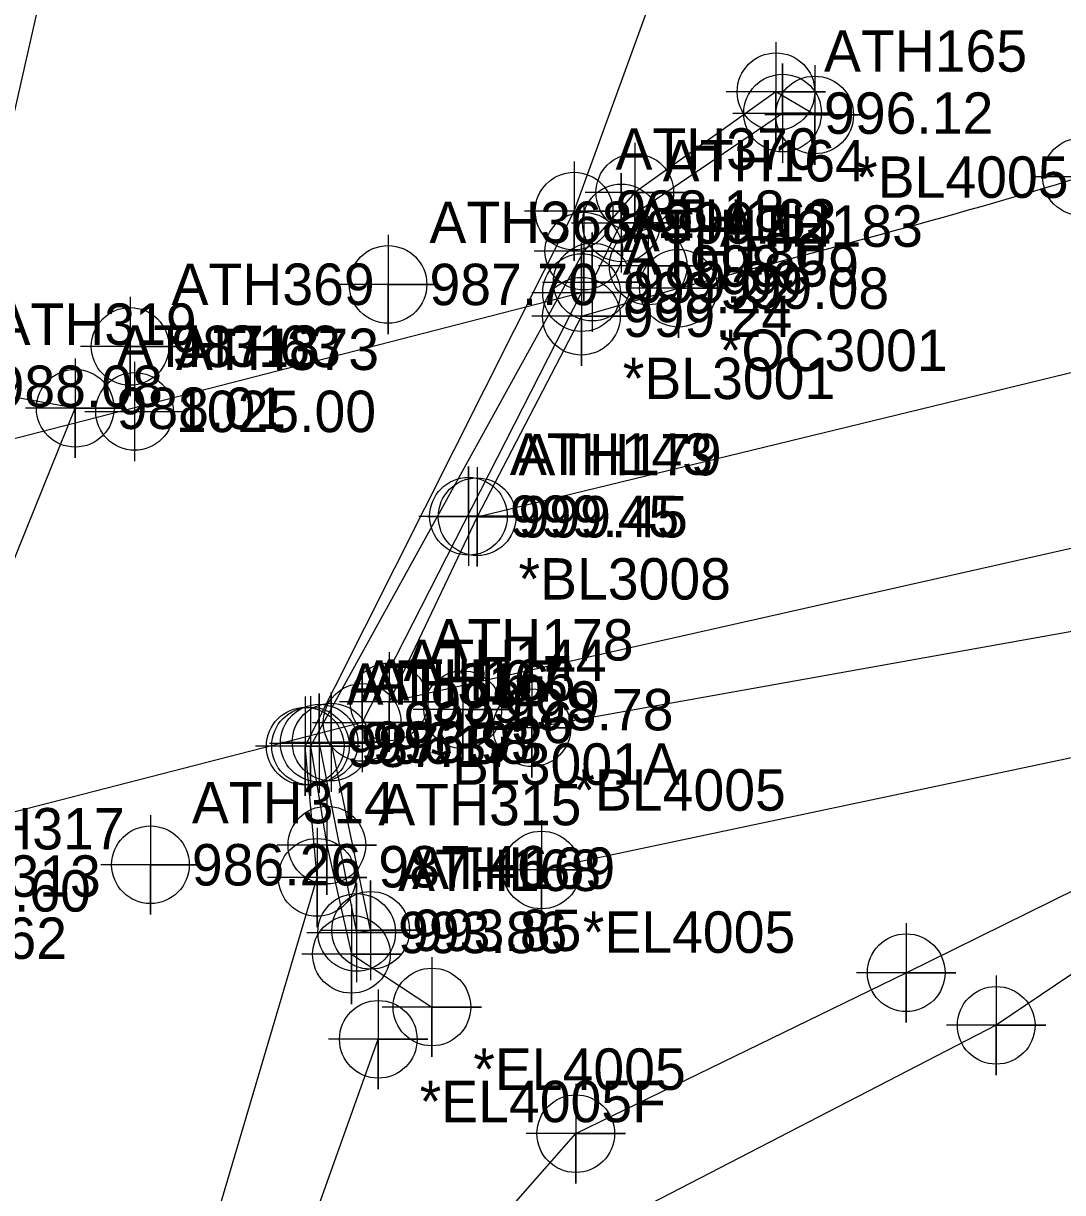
# Model space of a CAD drawing. Extents: x 1116680 to 1117499, y 661040 to 661703.
# Drawn here: x 1117062.7 to 1117125.5, y 661332.7 to 661403.3 of the extents above; entities that cross this region are included whole.
import ezdxf

# ---------------------------------------------------------------- set-up
doc = ezdxf.new("R2010")
doc.units = 0
for name, color, linetype in [('Cogo Default Point CELL', 7, 'Continuous'), ('COGO Default Point Elevation', 7, 'Continuous'), ('COGO Default Point Number', 7, 'Continuous'), ('Exist DTM Breakline', 7, 'Continuous'), ('Exist DTM Breakline Cogo Comment', 7, 'Continuous'), ('Exist DTM Breakline Cogo Point CELL', 7, 'Continuous'), ('Exist DTM Crownline', 7, 'Continuous'), ('Exist DTM Crownline Cogo Comment', 7, 'Continuous'), ('Exist DTM Crownline Cogo Elevation', 7, 'Continuous'), ('Exist DTM Crownline Cogo Number', 7, 'Continuous'), ('Exist DTM Crownline Cogo Point CELL', 7, 'Continuous'), ('Exist DTM Drainline Cogo Elevation', 7, 'Continuous'), ('Exist DTM Drainline Cogo Number', 7, 'Continuous'), ('Exist DTM Drainline Cogo Point CELL', 7, 'Continuous'), ('Exist DTM Regular Point Underwater CELL', 7, 'Continuous'), ('Exist DTM Regular Point Underwater Cogo Elevation', 7, 'Continuous'), ('Exist DTM Regular Point Underwater Cogo Number', 7, 'Continuous'), ('Exist Guardrail Cogo Elevation', 7, 'Continuous'), ('Exist Guardrail Cogo Point CELL', 7, 'Continuous'), ('Exist Hydro Stream or Body of Water', 7, 'Continuous'), ('Exist Roads EOP', 7, 'Continuous'), ('Exist Roads EOP Cogo Comment', 7, 'Continuous'), ('Exist Roads EOP Cogo Elevation', 7, 'Continuous'), ('Exist Roads EOP Cogo Number', 7, 'Continuous'), ('Exist Roads EOP Cogo Point CELL', 7, 'Continuous'), ('Exist Structure Major Bridge Seam Cogo Elevation', 7, 'Continuous'), ('Exist Structure Major Bridge Seam Cogo Number', 7, 'Continuous'), ('Exist Structure Major Bridge Seam Cogo Point CELL', 7, 'Continuous'), ('Exist Structure Major Bridge WW Cogo Elevation', 7, 'Continuous'), ('Exist Structure Major Bridge WW Cogo Number', 7, 'Continuous'), ('Exist Structure Major Bridge WW Cogo Point CELL', 7, 'Continuous'), ('Exist Structure Major Deck Tunnel Box Culvert', 7, 'Continuous')]:
    doc.layers.add(name, color=color, linetype=linetype)

msp = doc.modelspace()

# ---------------------------------------------------------------- linework, layer by layer
at = {"layer": 'Cogo Default Point CELL'}
for points in [[(1117069.447, 661382.896), (1117069.447, 661379.896)], [(1117066.447, 661379.896), (1117069.447, 661379.896)], [(1117069.447, 661379.896), (1117072.447, 661379.896)], [(1117069.447, 661379.896), (1117069.447, 661376.896)]]:
    msp.add_lwpolyline(points, dxfattribs=at)
msp.add_circle((1117069.447, 661379.896), 2.344, dxfattribs=at)
at = {"layer": 'Exist DTM Breakline'}
msp.add_line((1117136.948, 661361.295), (1117094.014, 661352.219), dxfattribs=at)
for points in [[(1117110.514, 661397.787), (1117108.176, 661399.189), (1117099.651, 661393.108), (1117096.571, 661389.572), (1117080.072, 661359.7), (1117081.059, 661353.723), (1117082.542, 661347.13), (1117087.401, 661343.949)], [(1117097.08, 661387.704), (1117098.837, 661391.274), (1117108.577, 661397.9)], [(1117093.445, 661360.799), (1117137.626, 661368.708), (1117143.021, 661357.384), (1117121.473, 661342.844), (1117095.236, 661329.298), (1117090.897, 661311.231), (1117084.978, 661291.24), (1117074.985, 661245.735)], [(1117081.313, 661359.936), (1117080.595, 661359.877), (1117082.857, 661348.449), (1117083.703, 661348.578), (1117081.313, 661359.936)], [(1117067.72, 661245.781), (1117079.092, 661299.504), (1117088.264, 661327.406), (1117096.09, 661336.305), (1117116.041, 661346.019), (1117139.594, 661357.628)], [(1117040.467, 661266.201), (1117071.81, 661307.445), (1117084.165, 661341.998)]]:
    msp.add_lwpolyline(points, dxfattribs=at)
at = {"layer": 'Exist DTM Breakline Cogo Point CELL'}
for points in [[(1117108.176, 661402.189), (1117108.176, 661396.189), (1117108.176, 661399.189), (1117111.176, 661399.189), (1117105.176, 661399.189)], [(1117110.514, 661400.787), (1117110.514, 661394.787), (1117110.514, 661397.787), (1117113.514, 661397.787), (1117107.514, 661397.787)], [(1117099.651, 661396.108), (1117099.651, 661390.108), (1117099.651, 661393.108), (1117102.651, 661393.108), (1117096.651, 661393.108)], [(1117096.571, 661392.572), (1117096.571, 661386.572), (1117096.571, 661389.572), (1117099.571, 661389.572), (1117093.571, 661389.572)], [(1117093.445, 661363.799), (1117093.445, 661357.799), (1117093.445, 661360.799), (1117096.445, 661360.799), (1117090.445, 661360.799)], [(1117080.072, 661362.7), (1117080.072, 661356.7), (1117080.072, 661359.7), (1117083.072, 661359.7), (1117077.072, 661359.7)], [(1117081.059, 661356.723), (1117081.059, 661350.723), (1117081.059, 661353.723), (1117084.059, 661353.723), (1117078.059, 661353.723)], [(1117094.014, 661355.219), (1117094.014, 661349.219), (1117094.014, 661352.219), (1117097.014, 661352.219), (1117091.014, 661352.219)], [(1117082.542, 661350.13), (1117082.542, 661344.13), (1117082.542, 661347.13), (1117085.542, 661347.13), (1117079.542, 661347.13)], [(1117116.041, 661349.019), (1117116.041, 661343.019), (1117116.041, 661346.019), (1117119.041, 661346.019), (1117113.041, 661346.019)], [(1117087.401, 661346.949), (1117087.401, 661340.949), (1117087.401, 661343.949), (1117090.401, 661343.949), (1117084.401, 661343.949)], [(1117121.473, 661345.844), (1117121.473, 661339.844), (1117121.473, 661342.844), (1117124.473, 661342.844), (1117118.473, 661342.844)], [(1117084.165, 661344.998), (1117084.165, 661338.998), (1117084.165, 661341.998), (1117087.165, 661341.998), (1117081.165, 661341.998)], [(1117096.09, 661339.305), (1117096.09, 661333.305), (1117096.09, 661336.305), (1117099.09, 661336.305), (1117093.09, 661336.305)]]:
    msp.add_lwpolyline(points, dxfattribs=at)
for centre in [(1117108.176, 661399.189), (1117110.514, 661397.787), (1117099.651, 661393.108), (1117096.571, 661389.572), (1117093.445, 661360.799), (1117080.072, 661359.7), (1117081.059, 661353.723), (1117094.014, 661352.219), (1117082.542, 661347.13), (1117116.041, 661346.019), (1117087.401, 661343.949), (1117121.473, 661342.844), (1117084.165, 661341.998), (1117096.09, 661336.305)]:
    msp.add_circle(centre, 2.344, dxfattribs=at)
at = {"layer": 'Exist DTM Crownline'}
msp.add_line((1117090.13, 661373.539), (1117128.608, 661382.881), dxfattribs=at)
at = {"layer": 'Exist DTM Crownline Cogo Point CELL'}
msp.add_lwpolyline([(1117090.13, 661376.539), (1117090.13, 661370.539), (1117090.13, 661373.539), (1117093.13, 661373.539), (1117087.13, 661373.539)], dxfattribs=at)
msp.add_circle((1117090.13, 661373.539), 2.344, dxfattribs=at)
at = {"layer": 'Exist DTM Drainline Cogo Point CELL'}
for points in [[(1117095.986, 661394.983), (1117095.986, 661388.983), (1117095.986, 661391.983), (1117098.986, 661391.983), (1117092.986, 661391.983)], [(1117065.864, 661383.085), (1117065.864, 661377.085), (1117065.864, 661380.085), (1117068.864, 661380.085), (1117062.864, 661380.085)], [(1117079.751, 661362.687), (1117079.751, 661356.687), (1117079.751, 661359.687), (1117082.751, 661359.687), (1117076.751, 661359.687)], [(1117080.473, 661354.773), (1117080.473, 661348.773), (1117080.473, 661351.773), (1117083.473, 661351.773), (1117077.473, 661351.773)]]:
    msp.add_lwpolyline(points, dxfattribs=at)
for centre in [(1117095.986, 661391.983), (1117065.864, 661380.085), (1117079.751, 661359.687), (1117080.473, 661351.773)]:
    msp.add_circle(centre, 2.344, dxfattribs=at)
at = {"layer": 'Exist DTM Regular Point Underwater CELL'}
for points in [[(1117084.753, 661390.559), (1117084.753, 661384.559), (1117084.753, 661387.559), (1117087.753, 661387.559), (1117081.753, 661387.559)], [(1117069.181, 661386.82), (1117069.181, 661380.82), (1117069.181, 661383.82), (1117072.181, 661383.82), (1117066.181, 661383.82)], [(1117070.409, 661355.534), (1117070.409, 661349.534), (1117070.409, 661352.534), (1117073.409, 661352.534), (1117067.409, 661352.534)]]:
    msp.add_lwpolyline(points, dxfattribs=at)
for centre in [(1117084.753, 661387.559), (1117069.181, 661383.82), (1117070.409, 661352.534)]:
    msp.add_circle(centre, 2.344, dxfattribs=at)
at = {"layer": 'Exist Guardrail Cogo Point CELL'}
for points in [[(1117100.46, 661391.675), (1117100.46, 661385.675), (1117100.46, 661388.675), (1117103.46, 661388.675), (1117097.46, 661388.675)], [(1117089.265, 661364.896), (1117089.265, 661358.896), (1117089.265, 661361.896), (1117092.265, 661361.896), (1117086.265, 661361.896)]]:
    msp.add_lwpolyline(points, dxfattribs=at)
for centre in [(1117100.46, 661388.675), (1117089.265, 661361.896)]:
    msp.add_circle(centre, 2.344, dxfattribs=at)
at = {"layer": 'Exist Hydro Stream or Body of Water'}
for points in [[(1116885.259, 661065.084), (1116909.522, 661128.826), (1116941.429, 661187.261), (1116973.299, 661231.015), (1117008.806, 661288.675), (1117028.625, 661329.39), (1117037.259, 661346.044), (1117054.084, 661350.959), (1117065.864, 661380.085), (1117058.435, 661381.413), (1117066.561, 661417.266), (1117077.352, 661449.252), (1117098.924, 661488.98)], [(1116999.252, 661212.663), (1117035.553, 661269.03), (1117067.842, 661309.057), (1117080.473, 661351.773), (1117079.751, 661359.687), (1117095.986, 661391.983), (1117110.725, 661432.453), (1117125.362, 661468.034)]]:
    msp.add_lwpolyline(points, dxfattribs=at)
at = {"layer": 'Exist Roads EOP'}
for p, q in [((1117096.428, 661385.641), (1117102.286, 661387.333)), ((1117084.815, 661362.36), (1117131.334, 661372.856))]:
    msp.add_line(p, q, dxfattribs=at)
msp.add_lwpolyline([(1117096.428, 661385.641), (1117090.13, 661373.539), (1117084.815, 661362.36)], dxfattribs=at)
msp.add_spline([(1117102.286, 661387.333), (1117126.621, 661394.057), (1117156.418, 661404.979), (1117187.204, 661421.689), (1117219.891, 661448.41), (1117247.012, 661480.823), (1117275.546, 661531.18), (1117296.661, 661577.27), (1117320.803, 661635.676)], degree=3, dxfattribs=at)
at = {"layer": 'Exist Roads EOP Cogo Point CELL'}
for points in [[(1117126.621, 661397.057), (1117126.621, 661391.057), (1117126.621, 661394.057), (1117129.621, 661394.057), (1117123.621, 661394.057)], [(1117102.286, 661390.333), (1117102.286, 661384.333), (1117102.286, 661387.333), (1117105.286, 661387.333), (1117099.286, 661387.333)], [(1117096.428, 661388.641), (1117096.428, 661382.641), (1117096.428, 661385.641), (1117099.428, 661385.641), (1117093.428, 661385.641)], [(1117084.815, 661365.36), (1117084.815, 661359.36), (1117084.815, 661362.36), (1117087.815, 661362.36), (1117081.815, 661362.36)]]:
    msp.add_lwpolyline(points, dxfattribs=at)
for centre in [(1117126.621, 661394.057), (1117102.286, 661387.333), (1117096.428, 661385.641), (1117084.815, 661362.36)]:
    msp.add_circle(centre, 2.344, dxfattribs=at)
at = {"layer": 'Exist Structure Major Bridge Seam Cogo Point CELL'}
for points in [[(1117093.438, 661387.065), (1117099.438, 661387.065), (1117096.438, 661387.065), (1117096.438, 661390.065), (1117096.438, 661384.065)], [(1117086.61, 661373.568), (1117092.61, 661373.568), (1117089.61, 661373.568), (1117089.61, 661376.568), (1117089.61, 661370.568)], [(1117080.188, 661361.127), (1117086.188, 661361.127), (1117083.188, 661361.127), (1117083.188, 661364.127), (1117083.188, 661358.127)]]:
    msp.add_lwpolyline(points, dxfattribs=at)
for centre in [(1117096.438, 661387.065), (1117089.61, 661373.568), (1117083.188, 661361.127)]:
    msp.add_circle(centre, 2.344, dxfattribs=at)
at = {"layer": 'Exist Structure Major Bridge WW Cogo Point CELL'}
for points in [[(1117105.577, 661397.9), (1117111.577, 661397.9), (1117108.577, 661397.9), (1117108.577, 661400.9), (1117108.577, 661394.9)], [(1117095.837, 661391.274), (1117101.837, 661391.274), (1117098.837, 661391.274), (1117098.837, 661394.274), (1117098.837, 661388.274)], [(1117094.08, 661387.704), (1117100.08, 661387.704), (1117097.08, 661387.704), (1117097.08, 661390.704), (1117097.08, 661384.704)], [(1117077.595, 661359.877), (1117083.595, 661359.877), (1117080.595, 661359.877), (1117080.595, 661362.877), (1117080.595, 661356.877)], [(1117078.313, 661359.936), (1117084.313, 661359.936), (1117081.313, 661359.936), (1117081.313, 661362.936), (1117081.313, 661356.936)], [(1117079.857, 661348.449), (1117085.857, 661348.449), (1117082.857, 661348.449), (1117082.857, 661351.449), (1117082.857, 661345.449)], [(1117080.703, 661348.578), (1117086.703, 661348.578), (1117083.703, 661348.578), (1117083.703, 661351.578), (1117083.703, 661345.578)]]:
    msp.add_lwpolyline(points, dxfattribs=at)
for centre in [(1117108.577, 661397.9), (1117098.837, 661391.274), (1117097.08, 661387.704), (1117080.595, 661359.877), (1117081.313, 661359.936), (1117082.857, 661348.449), (1117083.703, 661348.578)]:
    msp.add_circle(centre, 2.344, dxfattribs=at)
at = {"layer": 'Exist Structure Major Deck Tunnel Box Culvert'}
msp.add_lwpolyline([(1117031.737, 661370.434), (1117096.438, 661387.065), (1117083.188, 661361.127), (1117020.55, 661345.005), (1117031.737, 661370.434)], dxfattribs=at)

# ---------------------------------------------------------------- texts
at = {"layer": 'COGO Default Point Elevation'}
msp.add_text('1025.00', height=2.5, dxfattribs=at).set_placement((1117071.947, 661378.646))
at = {"layer": 'COGO Default Point Number'}
msp.add_text('ATH373', height=2.5, dxfattribs=at).set_placement((1117071.947, 661382.396))
at = {"layer": 'Exist DTM Breakline Cogo Comment'}
for s, p in [('*BL4005', (1117113.014, 661392.787)), ('*BL4005', (1117095.945, 661355.799)), ('*EL4005', (1117096.514, 661347.219)), ('*EL4005', (1117089.901, 661338.949)), ('*EL4005F', (1117086.665, 661336.998))]:
    msp.add_text(s, height=2.5, dxfattribs=at).set_placement(p)
at = {"layer": 'Exist DTM Crownline Cogo Comment'}
msp.add_text('*BL3008', height=2.5, dxfattribs=at).set_placement((1117092.63, 661368.539))
at = {"layer": 'Exist DTM Crownline Cogo Elevation'}
msp.add_text('999.45', height=2.5, dxfattribs=at).set_placement((1117092.63, 661372.289))
at = {"layer": 'Exist DTM Crownline Cogo Number'}
msp.add_text('ATH179', height=2.5, dxfattribs=at).set_placement((1117092.63, 661376.039))
at = {"layer": 'Exist DTM Drainline Cogo Elevation'}
for s, p in [('988.18', (1117098.486, 661390.733)), ('988.08', (1117060.935, 661380.163)), ('988.01', (1117068.364, 661378.835)), ('987.17', (1117082.251, 661358.437)), ('987.46', (1117084.166, 661351.166)), ('987.60', (1117056.584, 661349.709))]:
    msp.add_text(s, height=2.5, dxfattribs=at).set_placement(p)
at = {"layer": 'Exist DTM Drainline Cogo Number'}
for s, p in [('ATH370', (1117098.486, 661394.483)), ('ATH319', (1117060.935, 661383.913)), ('ATH318', (1117068.364, 661382.585)), ('ATH316', (1117082.251, 661362.187)), ('ATH315', (1117084.166, 661354.916)), ('ATH317', (1117056.584, 661353.459))]:
    msp.add_text(s, height=2.5, dxfattribs=at).set_placement(p)
at = {"layer": 'Exist DTM Regular Point Underwater Cogo Elevation'}
for s, p in [('987.70', (1117087.253, 661386.309)), ('987.63', (1117071.681, 661382.57)), ('986.26', (1117072.909, 661351.284)), ('987.62', (1117055.144, 661346.854))]:
    msp.add_text(s, height=2.5, dxfattribs=at).set_placement(p)
at = {"layer": 'Exist DTM Regular Point Underwater Cogo Number'}
for s, p in [('ATH368', (1117087.253, 661390.059)), ('ATH369', (1117071.681, 661386.32)), ('ATH314', (1117072.909, 661355.034)), ('ATH313', (1117055.144, 661350.604))]:
    msp.add_text(s, height=2.5, dxfattribs=at).set_placement(p)
at = {"layer": 'Exist Guardrail Cogo Elevation'}
for s, p in [('998.59', (1117102.96, 661387.425)), ('998.78', (1117091.765, 661360.646))]:
    msp.add_text(s, height=2.5, dxfattribs=at).set_placement(p)
at = {"layer": 'Exist Roads EOP Cogo Comment'}
for s, p in [('*OC3001', (1117104.786, 661382.333)), ('*BL3001', (1117098.928, 661380.641)), ('*BL3001A', (1117087.315, 661357.36))]:
    msp.add_text(s, height=2.5, dxfattribs=at).set_placement(p)
at = {"layer": 'Exist Roads EOP Cogo Elevation'}
for s, p in [('999.08', (1117104.786, 661386.083)), ('999.24', (1117098.928, 661384.391)), ('999.29', (1117087.315, 661361.11))]:
    msp.add_text(s, height=2.5, dxfattribs=at).set_placement(p)
at = {"layer": 'Exist Roads EOP Cogo Number'}
for s, p in [('ATH183', (1117104.786, 661389.833)), ('ATH180', (1117098.928, 661388.141)), ('ATH178', (1117087.315, 661364.86))]:
    msp.add_text(s, height=2.5, dxfattribs=at).set_placement(p)
at = {"layer": 'Exist Structure Major Bridge Seam Cogo Elevation'}
for s, p in [('999.22', (1117098.938, 661385.815)), ('999.45', (1117092.11, 661372.318)), ('999.56', (1117085.688, 661359.877))]:
    msp.add_text(s, height=2.5, dxfattribs=at).set_placement(p)
at = {"layer": 'Exist Structure Major Bridge Seam Cogo Number'}
for s, p in [('ATH142', (1117098.938, 661389.565)), ('ATH143', (1117092.11, 661376.068)), ('ATH144', (1117085.688, 661363.627))]:
    msp.add_text(s, height=2.5, dxfattribs=at).set_placement(p)
at = {"layer": 'Exist Structure Major Bridge WW Cogo Elevation'}
for s, p in [('996.12', (1117111.077, 661396.65)), ('999.12', (1117101.337, 661390.024)), ('999.09', (1117099.58, 661386.454)), ('996.93', (1117083.813, 661358.686)), ('996.58', (1117083.095, 661358.627)), ('993.86', (1117085.357, 661347.199)), ('993.85', (1117086.203, 661347.328))]:
    msp.add_text(s, height=2.5, dxfattribs=at).set_placement(p)
at = {"layer": 'Exist Structure Major Bridge WW Cogo Number'}
for s, p in [('ATH165', (1117111.077, 661400.4)), ('ATH164', (1117101.337, 661393.774)), ('ATH163', (1117099.58, 661390.204)), ('ATH167', (1117083.095, 661362.377)), ('ATH166', (1117083.813, 661362.436)), ('ATH168', (1117085.357, 661350.949)), ('ATH169', (1117086.203, 661351.078))]:
    msp.add_text(s, height=2.5, dxfattribs=at).set_placement(p)

doc.saveas('drawing.dxf')
